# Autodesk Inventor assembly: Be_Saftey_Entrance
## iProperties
Shininess: 64.0
Length Units: 11269
Angle Units: 11279
Time Units: 11290
Mass Units: 11283
Length Display Precision: 3
Angle Display Precision: 2
Compacted: True
Created: 2004-07
Part Number: Be_Saftey_Entrance
Document SubType Name: Assembly
Designer: John Blackburn
Manufacturer: Standard
Standards Organization: Custom
Density: 0.0
Volumn: 0.0
Area: 0.0
PropertySet Name: Model Information
Control State: 0
Master: False
Checked Out: False
Author: John Blackburn
